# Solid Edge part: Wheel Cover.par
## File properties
Author: m_hel
Template: iso metric part.par
Last saved by: m_hel
Revision: 2
Application: Solid Edge
Accuracy: 0,990
Username: m_hel
Material: Rubber
Face Style: Black (dull)
Fill Style: Normal
Virtual Style: Normal
Grouping: Uncategorized
LibraryName: Custom Materials
Coef. of Thermal Exp: 0.0
Thermal Conductivity: 0.0
Specific Heat: 0.0
Modulus of Elasticity: 0.0
Poisson's Ratio: 0.0
Yield Stress: 0.0
Ultimate Stress: 0.0
Elongation: 0.0
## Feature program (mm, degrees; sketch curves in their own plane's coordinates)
sketch for "unnamed Protrusion 1" plane through (0, 0, 0) normal (0, 0, 1) x-axis (1, 0, 0)
  circle centre (0, 0) radius 75
extrude "unnamed Protrusion 1" add finite 150 along +normal
sketch for "unnamed RevolvedCutout 1" plane through (0, 0, 0) normal (0, -1, 0) x-axis (1, 0, 0)
  line (38.2051, 140) -> (38.2051, 150)
  line (48.2051, 140) -> (38.2051, 140)
  line (75, 40) -> (48.2051, 140)
  line (65, 40) -> (75, 40)
  line (65, 10) -> (65, 40)
  line (25, 10) -> (65, 10)
  line (25, 0) -> (25, 10)
revolve "unnamed RevolvedCutout 1" cut finite 360 deg
sketch for "unnamed RevolvedCutout 2" plane through (-51.615, 0, 127.2741) normal (0, -1, 0) x-axis (1, 0, 0)
  arc centre (5.003, 9.0122) radius 2.5 from (4.356, 6.5974) to (2.5882, 9.6593) cw
  arc centre (3.7089, 4.1826) radius 2.5 from (3.0619, 1.7678) to (4.356, 6.5974) ccw
  arc centre (2.4148, -0.647) radius 2.5 from (0, 0) to (3.0619, 1.7678) cw
  arc centre (2.4148, -0.647) radius 2.5 from (1.7678, -3.0619) to (0, 0) cw
  arc centre (1.1207, -5.4767) radius 2.5 from (0.4737, -7.8915) to (1.7678, -3.0619) ccw
  arc centre (-0.1734, -10.3063) radius 2.5 from (-2.5882, -9.6593) to (0.4737, -7.8915) cw
  arc centre (-0.1734, -10.3063) radius 2.5 from (-0.8204, -12.7211) to (-2.5882, -9.6593) cw
  arc centre (-1.4675, -15.1359) radius 2.5 from (-2.1145, -17.5507) to (-0.8204, -12.7211) ccw
  arc centre (-2.7616, -19.9656) radius 2.5 from (-5.1764, -19.3185) to (-2.1145, -17.5507) cw
  arc centre (-2.7616, -19.9656) radius 2.5 from (-3.4086, -22.3804) to (-5.1764, -19.3185) cw
  arc centre (-4.0557, -24.7952) radius 2.5 from (-4.7027, -27.21) to (-3.4086, -22.3804) ccw
  arc centre (-5.3498, -29.6248) radius 2.5 from (-7.7646, -28.9778) to (-4.7027, -27.21) cw
  arc centre (-5.3498, -29.6248) radius 2.5 from (-5.9968, -32.0396) to (-7.7646, -28.9778) cw
  arc centre (-6.6439, -34.4545) radius 2.5 from (-7.2909, -36.8693) to (-5.9968, -32.0396) ccw
  arc centre (-7.9379, -39.2841) radius 2.5 from (-10.3528, -38.637) to (-7.2909, -36.8693) cw
  arc centre (-7.9379, -39.2841) radius 2.5 from (-8.585, -41.6989) to (-10.3528, -38.637) cw
  arc centre (-9.232, -44.1137) radius 2.5 from (-9.8791, -46.5285) to (-8.585, -41.6989) ccw
  arc centre (-10.5261, -48.9433) radius 2.5 from (-12.941, -48.2963) to (-9.8791, -46.5285) cw
  arc centre (-10.5261, -48.9433) radius 2.5 from (-11.1732, -51.3582) to (-12.941, -48.2963) cw
  arc centre (-11.8202, -53.773) radius 2.5 from (-12.4673, -56.1878) to (-11.1732, -51.3582) ccw
  arc centre (-13.1143, -58.6026) radius 2.5 from (-15.5291, -57.9555) to (-12.4673, -56.1878) cw
  arc centre (-13.1143, -58.6026) radius 2.5 from (-13.7614, -61.0174) to (-15.5291, -57.9555) cw
  arc centre (-14.4084, -63.4322) radius 2.5 from (-15.0555, -65.847) to (-13.7614, -61.0174) ccw
  arc centre (-15.7025, -68.2619) radius 2.5 from (-18.1173, -67.6148) to (-15.0555, -65.847) cw
  arc centre (-15.7025, -68.2619) radius 2.5 from (-16.3496, -70.6767) to (-18.1173, -67.6148) cw
  arc centre (-16.9966, -73.0915) radius 2.5 from (-17.6437, -75.5063) to (-16.3496, -70.6767) ccw
  arc centre (-18.2907, -77.9211) radius 2.5 from (-20.7055, -77.2741) to (-17.6437, -75.5063) cw
revolve "unnamed RevolvedCutout 2" cut finite 360 deg about sketch line (51.615, -10.1372) -> (51.615, -50.9389)
thinwall "Thinwall_1"  Thickness = 4 mm
sketch for "unnamed Cutout 1" plane through (0, 0, 150) normal (0, 0, 1) x-axis (0, 1, 0)
  circle centre (0, 0) radius 15
extrude "unnamed Cutout 1" cut through along -normal
Other named dimensions: "PatternSurface_2": XDirCount = 9; XDirSpacing = 10 mm; YDirCount = 4; YDirSpacing = 26.8437 mm
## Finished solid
Body 1: solid body, 47 faces, 47 edges, 0 vertices.
  Faces by surface: torus 28, plane 9, cylinder 7, cone 3
  Edges by curve: circle 47
Bounding box of the edges (mm; curved faces can reach further): 150.000 x 150.000 x 150.000, from (-75, -75, 0) to (75, 75, 150).
Cylindrical faces by radius (mm): R15 x1, R21 x1, R25 x1, R34.2051 x1, R38.2051 x1, R61 x1, R65 x1
Conical faces (half-angle, radius in mm at the cone's reference point): 15 deg R44.3414 x1, 15 deg R48.2051 x2
Toroidal faces (ring radius, tube radius in mm): R46.612 r2.5 x1, R47.9061 r2.5 x1, R47.9061 r6.5 x1, R49.2002 r2.5 x1, R50.4943 r2.5 x1, R50.4943 r6.5 x1, R51.7884 r2.5 x1, R53.0825 r2.5 x1, R53.0825 r6.5 x1, R54.3766 r2.5 x1, R55.6706 r2.5 x1, R55.6706 r6.5 x1, R56.9647 r2.5 x1, R58.2588 r2.5 x1, R58.2588 r6.5 x1, R59.5529 r2.5 x1, R60.847 r2.5 x1, R60.847 r6.5 x1, R62.1411 r2.5 x1, R63.4352 r2.5 x1, R63.4352 r6.5 x1, R64.7293 r2.5 x1, R66.0234 r2.5 x1, R66.0234 r6.5 x1, R67.3175 r2.5 x1, R68.6116 r2.5 x1, R68.6116 r6.5 x1, R69.9057 r2.5 x1
Planar faces by outward normal: +z 4, -z 5
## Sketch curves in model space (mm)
line (-72.3205, 0, 50) -> (-51.518, 0, 127.6359)
line (0, 0, 66.1386) -> (0, 0, 94.7271)
arc centre (-68.6116, 0, 54.1826) radius 2.5 from (-69.2586, 0, 51.7678) through (-66.1787, 0, 53.6074) to (-67.9646, 0, 56.5974)
arc centre (-67.3175, 0, 59.0122) radius 2.5 from (-67.9646, 0, 56.5974) through (-69.518, 0, 57.8257) to (-69.7323, 0, 59.6593)
line (-72.3205, 0, 50) -> (-69.7323, 0, 59.6593)
arc centre (-69.9057, 0, 49.353) radius 2.5 from (-72.3205, 0, 50) through (-71.0922, 0, 51.5535) to (-69.2586, 0, 51.7678)
line (0, 0, 147.4824) -> (0, 0, 37.2878)
line (38.2051, 0, 140) -> (38.2051, 0, 150)
line (48.2051, 0, 140) -> (38.2051, 0, 140)
line (75, 0, 40) -> (48.2051, 0, 140)
line (65, 0, 40) -> (75, 0, 40)
line (65, 0, 10) -> (65, 0, 40)
line (25, 0, 10) -> (65, 0, 10)
line (25, 0, 0) -> (25, 0, 10)
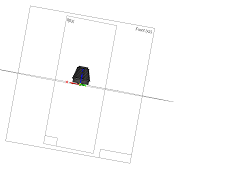
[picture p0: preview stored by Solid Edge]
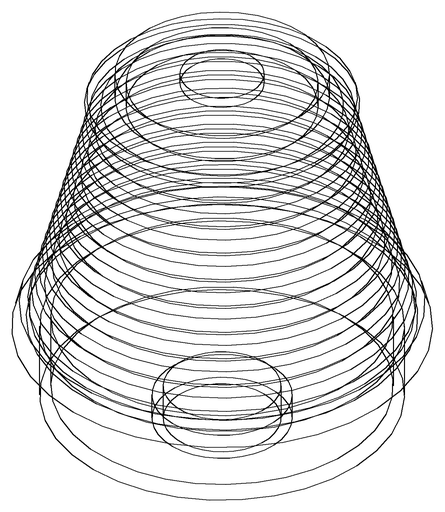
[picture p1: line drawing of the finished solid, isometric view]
